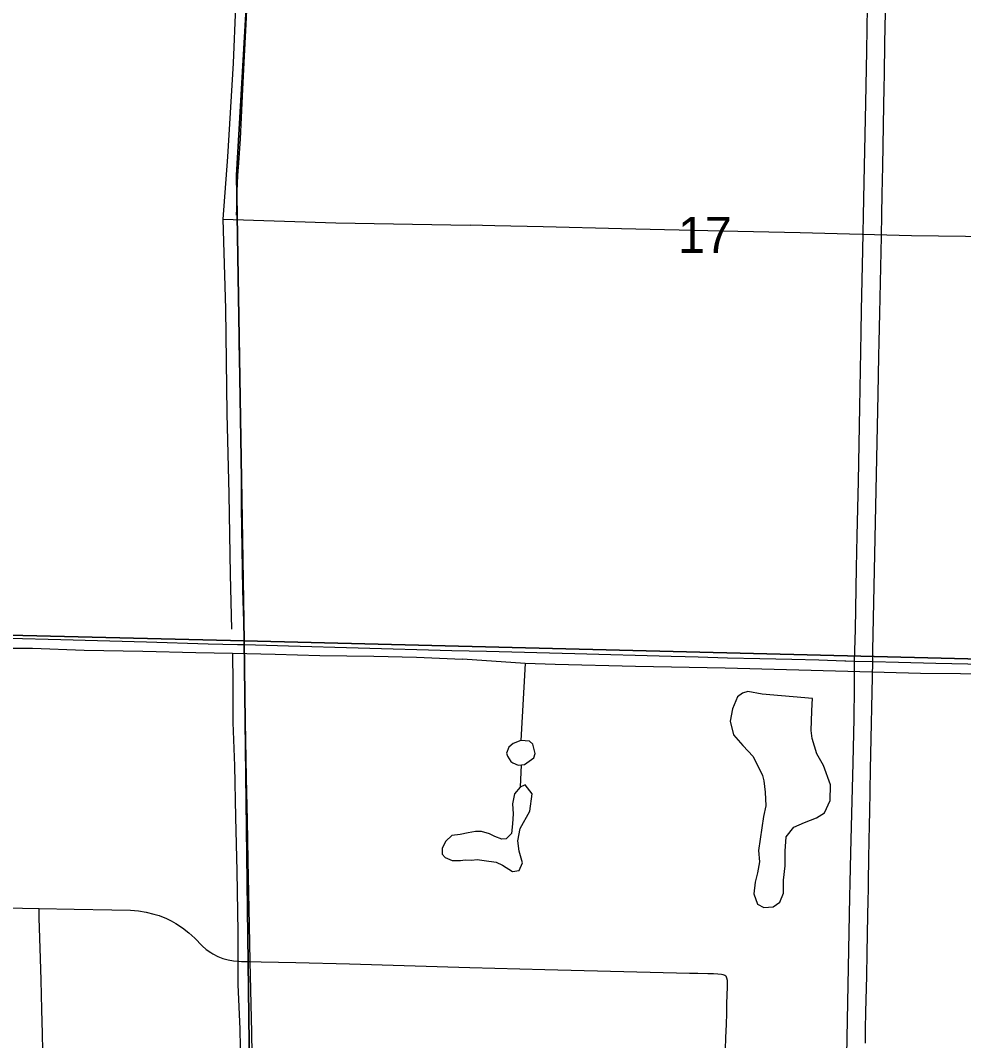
# Model space of a CAD drawing. Extents: x -59 to 43, y 0 to 22.
# Drawn here: x 26.006 to 27.1, y 17.807 to 18.99 of the extents above; entities that cross this region are included whole.
import ezdxf

# ---------------------------------------------------------------- set-up
doc = ezdxf.new("R2010")
doc.units = 0
for name, color, linetype in [('GM_X_City_Street', 7, 'Continuous'), ('GM_X_County_Road', 7, 'Continuous'), ('GM_X_Interstate_Route', 7, 'Continuous'), ('GM_X_Minor_Lake', 7, 'Continuous'), ('GM_X_Minor_River', 7, 'Continuous'), ('GM_X_Section', 7, 'Continuous'), ('GM_X_Section_Text', 7, 'Continuous'), ('GM_X_Township_Road', 7, 'Continuous')]:
    doc.layers.add(name, color=color, linetype=linetype)

msp = doc.modelspace()

# ---------------------------------------------------------------- linework, layer by layer
at = {"layer": 'GM_X_City_Street'}
for points in [[(25.9506, 17.9613), (26.0281, 17.9598), (26.0687, 17.9591), (26.1122, 17.9583), (26.1339, 17.9578), (26.1431, 17.957), (26.1523, 17.9556), (26.1612, 17.9534), (26.1671, 17.9516), (26.1757, 17.9482), (26.1813, 17.9455), (26.1866, 17.9425), (26.1943, 17.9374), (26.2017, 17.9318), (26.2085, 17.9256), (26.2171, 17.9166), (26.2218, 17.9124), (26.227, 17.9087), (26.2297, 17.9072), (26.2353, 17.9043), (26.2411, 17.9019), (26.2472, 17.9002), (26.2534, 17.8991), (26.2597, 17.8986), (26.2628, 17.8985), (26.2729, 17.8985)], [(26.0327, 17.7721), (26.0326, 17.7788), (26.0323, 17.7953), (26.0318, 17.8145), (26.0312, 17.8425), (26.0305, 17.8769), (26.0296, 17.9019), (26.0282, 17.9489), (26.0282, 17.952), (26.0281, 17.9598)], [(26.2729, 17.8985), (26.2855, 17.898), (26.3259, 17.8972), (26.388, 17.8955), (26.5277, 17.8916), (26.6146, 17.8892), (26.7823, 17.885), (26.7919, 17.885), (26.8038, 17.8846), (26.8104, 17.8843), (26.8152, 17.8841), (26.8195, 17.8837), (26.821, 17.8834), (26.8223, 17.883), (26.8235, 17.8824), (26.8244, 17.8816), (26.8251, 17.8804), (26.8255, 17.8793), (26.8259, 17.8769), (26.8261, 17.8744), (26.8259, 17.8669), (26.8256, 17.8613), (26.8254, 17.8479), (26.8252, 17.8382), (26.8249, 17.8258), (26.8242, 17.81), (26.8237, 17.7967)]]:
    msp.add_lwpolyline(points, dxfattribs=at)
at = {"layer": 'GM_X_County_Road'}
for points in [[(25.767, 18.2799), (25.7954, 18.2791), (25.8793, 18.2767), (25.9321, 18.2754), (25.9942, 18.2734), (26.0532, 18.2719), (26.1526, 18.2693), (26.224, 18.2669), (26.2582, 18.2662), (26.2661, 18.266)], [(26.2661, 18.266), (26.3172, 18.2646), (26.3979, 18.2623), (26.5067, 18.2593), (26.547, 18.2584), (26.6495, 18.2557), (26.7613, 18.2526), (26.7775, 18.2523), (26.7924, 18.2519), (26.8265, 18.2509), (26.8638, 18.25), (26.9011, 18.249), (26.9324, 18.2482), (26.9626, 18.2474), (26.9636, 18.2474)], [(26.2705, 18.0161), (26.2696, 18.0618), (26.2686, 18.1116), (26.2673, 18.177), (26.2661, 18.266)], [(26.9636, 18.2474), (26.9739, 18.247), (26.9949, 18.2465), (27.0247, 18.2457), (27.0681, 18.2447), (27.1053, 18.2436), (27.1519, 18.2423), (27.156, 18.2422)], [(26.2729, 17.8985), (26.272, 17.9404), (26.2705, 18.0151), (26.2705, 18.0161)], [(26.2756, 17.7653), (26.2747, 17.816), (26.2729, 17.8985)]]:
    msp.add_lwpolyline(points, dxfattribs=at)
at = {"layer": 'GM_X_Interstate_Route'}
for points in [[(26.9952, 18.2594), (27.0012, 18.5568), (27.0016, 18.5786), (27.0021, 18.6009), (27.0024, 18.6171), (27.0032, 18.6507), (27.0049, 18.7395), (27.0054, 18.765), (27.0059, 18.7886), (27.0065, 18.821), (27.0078, 18.8918), (27.0082, 18.9117), (27.0084, 18.9279), (27.0091, 18.9639), (27.0098, 19), (27.0102, 19.0162), (27.0116, 19.0814), (27.0123, 19.1224), (27.0125, 19.1374), (27.0128, 19.1579), (27.0134, 19.184), (27.0144, 19.2256), (27.0147, 19.2419), (27.0148, 19.2478)], [(26.9646, 17.7688), (26.9685, 17.9735), (26.9689, 17.9896), (26.9697, 18.0244), (26.9707, 18.0698), (26.9722, 18.1289), (26.9734, 18.1805), (26.9738, 18.2159), (26.9739, 18.247), (26.9748, 18.2836), (26.9761, 18.3551), (26.977, 18.3924), (26.9785, 18.4558), (26.98, 18.5416), (26.9815, 18.628), (26.982, 18.6541), (26.9834, 18.7237), (26.9846, 18.7834), (26.9855, 18.8213), (26.9869, 18.8941), (26.9881, 18.955), (26.9894, 19.0321)], [(26.9864, 17.8035), (26.9867, 17.8203), (26.987, 17.8396), (26.9879, 17.8818), (26.9884, 17.9079), (26.9893, 17.9521), (26.9896, 17.9689), (26.9899, 17.9826), (26.99, 17.9906), (26.9905, 18.0186), (26.9913, 18.0572), (26.9916, 18.0715), (26.9925, 18.1212), (26.9949, 18.2465), (26.9952, 18.2594)]]:
    msp.add_lwpolyline(points, dxfattribs=at)
at = {"layer": 'GM_X_Minor_Lake'}
for p, q in [((26.5714, 18.1366), (26.5753, 18.1306)), ((26.8682, 18.0668), (26.8625, 18.0271))]:
    msp.add_line(p, q, dxfattribs=at)
for points in [[(26.8625, 18.0271), (26.8636, 18.0141), (26.8614, 18.0012), (26.8584, 17.9903), (26.8569, 17.9767), (26.8611, 17.9648), (26.8686, 17.9611), (26.8796, 17.9619), (26.887, 17.9674), (26.8914, 17.9776), (26.8915, 17.9928), (26.8935, 18.0095), (26.8932, 18.0262), (26.8944, 18.0429), (26.9035, 18.0544), (26.9158, 18.0598), (26.9296, 18.0651), (26.9389, 18.0709), (26.9454, 18.0852), (26.9459, 18.1034), (26.9378, 18.1257), (26.9302, 18.1392), (26.9246, 18.1572), (26.9234, 18.1664), (26.9244, 18.1888), (26.9246, 18.1968), (26.9252, 18.2036), (26.8665, 18.2087), (26.8499, 18.2115), (26.8438, 18.2097), (26.8379, 18.2053), (26.8322, 18.1914), (26.8296, 18.1774), (26.8333, 18.1614), (26.8443, 18.1489), (26.8561, 18.1364), (26.8669, 18.114), (26.8686, 18.1079), (26.8701, 18.0949), (26.8708, 18.0789), (26.8682, 18.0668)], [(26.5753, 18.1306), (26.5773, 18.1288), (26.5836, 18.1263), (26.5909, 18.1269), (26.6017, 18.1345), (26.6034, 18.1398), (26.6007, 18.1505), (26.597, 18.1541), (26.5867, 18.1547), (26.5779, 18.1512), (26.5729, 18.1471), (26.57, 18.14), (26.5714, 18.1366)], [(26.5166, 18.0155), (26.5221, 18.0163), (26.5296, 18.0161), (26.5361, 18.0166), (26.5444, 18.0156), (26.5581, 18.0137), (26.5655, 18.0101), (26.5771, 18.0029), (26.5847, 18.0038), (26.5888, 18.0128), (26.585, 18.0263), (26.5834, 18.0385), (26.5861, 18.0528), (26.5973, 18.0727), (26.5998, 18.0928), (26.5917, 18.1033), (26.586, 18.1008), (26.5793, 18.093), (26.5771, 18.0812), (26.5779, 18.0698), (26.5772, 18.058), (26.5761, 18.0467), (26.5698, 18.0408), (26.5649, 18.0405), (26.5566, 18.0434), (26.5506, 18.0466), (26.5411, 18.0491), (26.534, 18.0494), (26.5256, 18.0476), (26.5164, 18.0459)], [(26.5164, 18.0459), (26.5069, 18.0446), (26.4999, 18.0379), (26.4956, 18.03), (26.4955, 18.0228), (26.4988, 18.0189), (26.5071, 18.0157), (26.5124, 18.0156), (26.5166, 18.0155)]]:
    msp.add_lwpolyline(points, dxfattribs=at)
at = {"layer": 'GM_X_Minor_River'}
for points in [[(26.2851, 19.8101), (26.2841, 19.657), (26.2774, 19.5024), (26.2738, 19.3755), (26.2687, 19.2448), (26.2612, 19.1089), (26.2558, 19.0064), (26.253, 18.9407), (26.2464, 18.8321), (26.2413, 18.7596), (26.2442, 18.6558), (26.2457, 18.5341), (26.2481, 18.4406), (26.2497, 18.3474), (26.2512, 18.2839)], [(26.2413, 18.7596), (26.3721, 18.7556), (26.5281, 18.7526)], [(27.1651, 18.7386), (27.0399, 18.7402), (26.9109, 18.7439), (26.8203, 18.7458), (26.7034, 18.7483), (26.6128, 18.7509), (26.5566, 18.7518), (26.5281, 18.7526)], [(25.5301, 18.2723), (25.6185, 18.2699), (25.6822, 18.2683), (25.7557, 18.2658), (25.8255, 18.2638), (25.8926, 18.2629), (25.9632, 18.2619), (26.0205, 18.262), (26.0804, 18.2597), (26.1483, 18.2585), (26.2097, 18.2569), (26.2522, 18.2561), (26.3018, 18.2548), (26.3538, 18.2535), (26.4164, 18.2527), (26.4657, 18.2514), (26.5191, 18.2492)], [(26.2522, 18.2561), (26.2526, 18.2208), (26.2529, 18.1755), (26.2546, 18.1253), (26.2558, 18.066), (26.2572, 18.0033), (26.2585, 17.9326), (26.2585, 17.8717), (26.2609, 17.82), (26.2617, 17.7782)], [(27.1431, 18.2316), (27.0505, 18.2327), (26.9659, 18.2348), (26.8237, 18.2388), (26.7198, 18.2407), (26.6264, 18.2429), (26.5919, 18.2443), (26.5191, 18.2492)], [(26.5919, 18.2443), (26.5867, 18.1547)], [(26.5872, 18.1266), (26.586, 18.1008)]]:
    msp.add_lwpolyline(points, dxfattribs=at)
at = {"layer": 'GM_X_Section'}
for points in [[(25.1962, 19.2843), (26.283, 19.2582), (26.2571, 18.8106), (26.2659, 18.2705), (25.1911, 18.2964), (25.1906, 18.3142)], [(26.283, 19.2582), (27.2913, 19.2374), (27.2918, 18.2449), (26.2659, 18.2705), (26.2571, 18.8106)], [(25.1911, 18.2964), (26.2659, 18.2705), (26.2782, 17.275), (25.1878, 17.2935), (25.1877, 17.3128)], [(26.2659, 18.2705), (27.2918, 18.2449), (27.273, 17.253), (26.2782, 17.275)]]:
    msp.add_lwpolyline(points, close=True, dxfattribs=at)
at = {"layer": 'GM_X_Township_Road'}
for points in [[(26.2587, 18.8103), (26.2597, 18.825), (26.2615, 18.8529), (26.2641, 18.9024), (26.2664, 18.9488), (26.2681, 18.9859), (26.2692, 19.01)], [(26.2571, 18.7645), (26.2572, 18.7718), (26.2573, 18.7827), (26.2581, 18.8009), (26.2587, 18.8103)], [(26.2661, 18.266), (26.2657, 18.2766), (26.2653, 18.2927), (26.2644, 18.3292), (26.2629, 18.4253), (26.2626, 18.4749), (26.2621, 18.5152), (26.2613, 18.5741), (26.26, 18.6144)]]:
    msp.add_lwpolyline(points, dxfattribs=at)

# ---------------------------------------------------------------- texts
at = {"layer": 'GM_X_Section_Text'}
msp.add_text('17', height=0.04186, rotation=0, dxfattribs=at).set_placement((26.7692, 18.7205))

doc.saveas('drawing.dxf')
